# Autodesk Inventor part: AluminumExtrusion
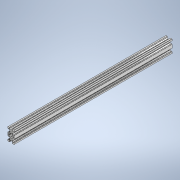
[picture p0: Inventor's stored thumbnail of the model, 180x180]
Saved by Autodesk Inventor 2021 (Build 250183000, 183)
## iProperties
Created: 2026-10
Part Number: AluminumExtrusion
Material: Aluminum 6061
Document SubType Name: Modeling
Designer: hp
Density: 2.7 g/cm^3
Appearance: Aluminum - Polished
Author: hp
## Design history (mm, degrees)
sketch "Sketch1"
  geometry: L1 (-10, -10)-(10, 10); L2 (2.839, -3.9)-(-2.839, -3.9); L3 (-3.9, -2.839)-(-3.9, 2.839); L4 (-2.839, 3.9)-(2.839, 3.9); L5 (3.9, 2.839)-(3.9, -2.839); L6 (3.9, -3.9)-(-3.9, 3.9); L7 (-3.9, -3.9)-(3.9, 3.9); L8 (-5.5, -8.28)-(-5.5, -6.561); L9 (-8.28, -5.5)-(-6.561, -5.5); L10 (-3.9, -2.839)-(-6.561, -5.5); L11 (-2.839, -3.9)-(-5.5, -6.561); L12 (0, -10)-(0, 10); L13 (5.5, -8.28)-(5.5, -6.561); L14 (2.839, -3.9)-(5.5, -6.561); L15 (3.9, -2.839)-(6.561, -5.5); L16 (-3.552, -8.707)-(-4.845, -10); L17 (-3.125, -8.28)-(-0.693, -8.28); L18 (3.552, -8.707)-(4.845, -10); L19 (-5.5, -8.28)-(-3.729, -8.28); L20 (3.729, -8.28)-(5.5, -8.28); L21 (10, -10)-(4.845, -10); L22 (-4.845, -10)-(-10, -10); L23 (-8.707, -3.552)-(-10, -4.845); L24 (-8.28, -5.5)-(-8.28, -3.729); L25 (-10, -4.845)-(-10, -10); L26 (8.707, -3.552)-(10, -4.845); L27 (8.28, -3.729)-(8.28, -5.5); L28 (8.28, -5.5)-(6.561, -5.5); L29 (10, -10)-(10, -4.845); L30 (-5.5, -8.28)-(-3.729, -8.28); L31 (-3.552, -8.707)-(-4.845, -10); L32 (3.125, -8.28)-(0.693, -8.28); L33 (5.5, -8.28)-(3.729, -8.28); L34 (5.5, -8.28)-(3.729, -8.28); L35 (3.9, -2.839)-(6.561, -5.5); L36 (3.9, -3.9)-(-3.9, 3.9); L37 (2.839, -3.9)-(5.5, -6.561); L38 (3.552, -8.707)-(4.845, -10); L39 (3.552, -8.707)-(4.845, -10); L40 (5.5, -8.28)-(5.5, -6.561); L41 (4.845, -10)-(10, -10); L42 (10, -4.845)-(10, -10); L43 (8.28, -5.5)-(6.561, -5.5); L44 (8.28, -5.5)-(8.28, -3.729); L45 (8.707, -3.552)-(10, -4.845); L46 (-10, 0)-(10, 0); L47 (-8.28, 5.5)-(-6.561, 5.5); L48 (-3.9, 2.839)-(-6.561, 5.5); L49 (2.839, 3.9)-(-2.839, 3.9); L50 (2.839, 3.9)-(5.5, 6.561); L51 (3.9, 2.839)-(6.561, 5.5); L52 (8.28, 3.729)-(8.28, 5.5); L53 (8.28, 5.5)-(8.28, 3.729); L54 (8.707, 3.552)-(10, 4.845); L55 (3.9, 2.839)-(6.561, 5.5); L56 (8.28, 5.5)-(6.561, 5.5); L57 (10, 10)-(10, 4.845); L58 (8.28, 5.5)-(6.561, 5.5); L59 (10, 4.845)-(10, 10); L60 (-8.28, 5.5)-(-8.28, 3.729); L61 (-8.707, 3.552)-(-10, 4.845); L62 (-10, 4.845)-(-10, 10); L63 (8.707, 3.552)-(10, 4.845); L64 (-10, -10)-(-10, -4.845)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; C1 r 2.1 at (0, 0); C2 r 2.1 at (0, 20); A1 r 0.25 centre (-8.53, -3.729) between (-8.28, -3.729) and (-8.707, -3.552); A2 r 0.25 centre (-3.729, -8.53) between (-3.552, -8.707) and (-3.729, -8.28); A3 r 0.25 centre (3.729, -8.53) between (3.729, -8.28) and (3.552, -8.707); A4 r 0.25 centre (8.53, -3.729) between (8.707, -3.552) and (8.28, -3.729); A5 r 0.25 centre (8.53, 3.729) between (8.28, 3.729) and (8.707, 3.552); A6 r 0.25 centre (-8.53, 3.729) between (-8.707, 3.552) and (-8.28, 3.729); A7 r 0.25 centre (3.729, 28.53) between (3.552, 28.707) and (3.729, 28.28); A8 r 0.25 centre (-8.53, 23.729) between (-8.707, 23.552) and (-8.28, 23.729); A9 r 0.25 centre (-3.729, 28.53) between (-3.729, 28.28) and (-3.552, 28.707); A10 r 0.25 centre (-8.53, 16.271) between (-8.28, 16.271) and (-8.707, 16.448); A11 r 0.25 centre (8.53, 16.271) between (8.707, 16.448) and (8.28, 16.271); A12 r 0.25 centre (8.53, 23.729) between (8.28, 23.729) and (8.707, 23.552); 2 further points
  constraints: 300 end point, 43 symmetric about line, 24 point on circle, 14 centre point, 8 parallel, 8 point on line, 7 perpendicular, 6 midpoint, 3 horizontal, 2 coincident, 2 tangent, 1 vertical, 5 other
  dimensions: "d0" = 4.2 diameter of C1; "d2" = 20 distance of L1.start L62.end; "d9" = 1.5 distance between parallel lines of L11 L10; "d12" = 6.25 distance of L17.start L32.start; "d14" = 45 deg angle of L16 L19; "d19" = 0.5 diameter of A1
extrude "Extrusion1" new body sketch "Sketch1" distance "d20" = 500; taper "d21" = 0 deg
fillet "Fillet1" dims "d22" = 0.5
fillet "Fillet2" dims "d23" = 0.5, "d24" = 0.5
body "Solid1"
other parameters: "d5" = 6.1, "d10" = 4.5
